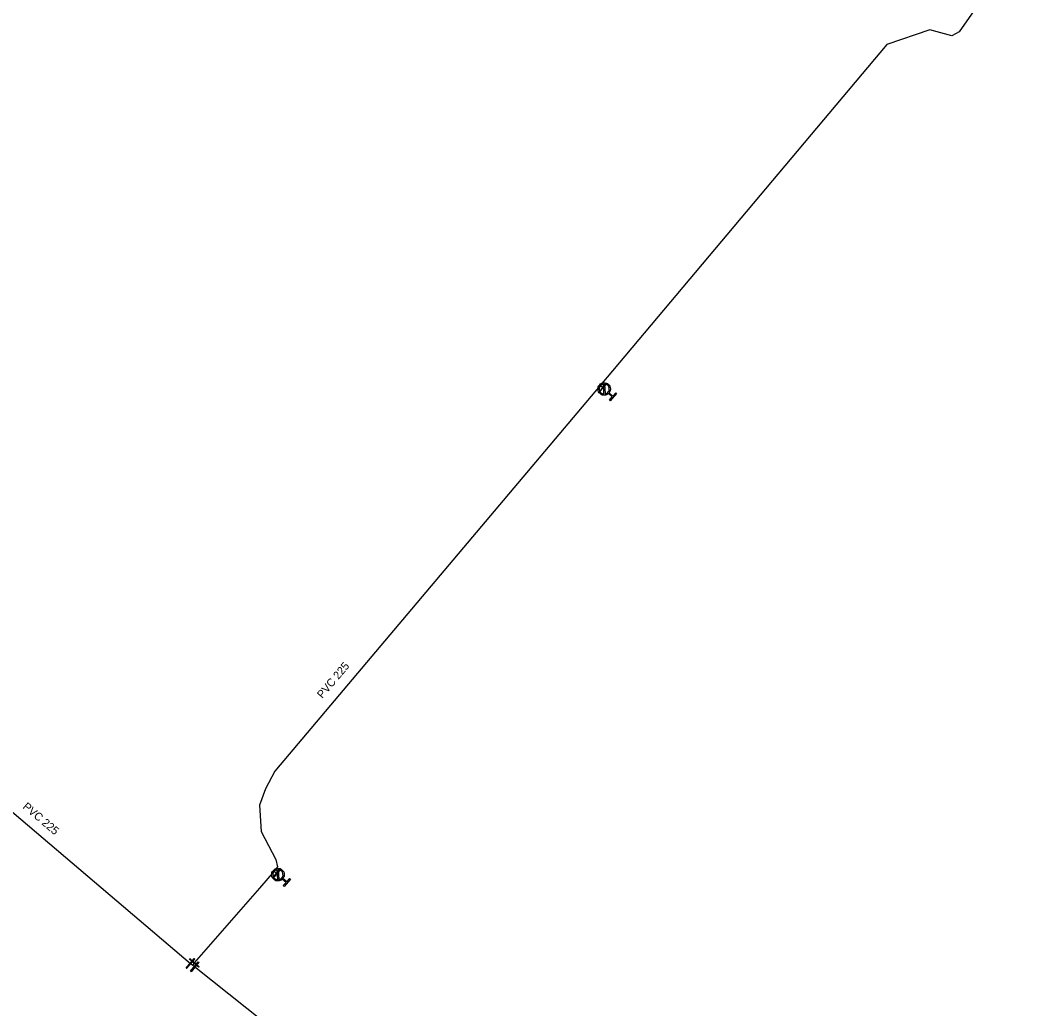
# Model space of a CAD drawing. Extents: x -643842 to -636370, y -1119190 to -1110210.
# Drawn here: x -640713.4 to -640550.3, y -1115738.1 to -1115577.6 of the extents above; entities that cross this region are included whole.
import ezdxf

# ---------------------------------------------------------------- set-up
doc = ezdxf.new("R2010")
doc.units = 0
for name, color, linetype in [('Default', 7, 'Continuous'), ('Level 16', 7, 'Continuous'), ('Level 20', 7, 'Continuous'), ('Level 21', 7, 'Continuous'), ('Level 23', 7, 'Continuous'), ('Level 33', 7, 'Continuous')]:
    doc.layers.add(name, color=color, linetype=linetype)

msp = doc.modelspace()

# ---------------------------------------------------------------- linework, layer by layer
at = {"layer": 'Default'}
for points in [[(-640617.92, -1115638.2), (-640618.18, -1115638.45), (-640618.55, -1115638.47), (-640618.96, -1115638.49), (-640619.27, -1115638.21), (-640619.58, -1115637.94), (-640619.6, -1115637.52), (-640619.62, -1115637.11), (-640619.34, -1115636.8), (-640619.07, -1115636.49), (-640618.66, -1115636.47), (-640618.24, -1115636.45), (-640617.93, -1115636.72), (-640617.62, -1115637), (-640617.6, -1115637.41), (-640617.58, -1115637.78), (-640617.8, -1115638.07)], [(-640618.73, -1115636.67), (-640619.01, -1115636.71), (-640619.2, -1115636.93), (-640619.43, -1115637.18), (-640619.41, -1115637.51), (-640619.39, -1115637.85), (-640619.14, -1115638.07), (-640618.92, -1115638.27), (-640618.65, -1115638.28)], [(-640618.46, -1115638.27), (-640618.19, -1115638.23), (-640617.99, -1115638.01), (-640617.77, -1115637.76), (-640617.78, -1115637.42), (-640617.8, -1115637.09), (-640618.05, -1115636.86), (-640618.27, -1115636.67), (-640618.55, -1115636.66)], [(-640670.88, -1115717.03), (-640671.14, -1115717.29), (-640671.5, -1115717.31), (-640671.92, -1115717.34), (-640672.23, -1115717.06), (-640672.54, -1115716.79), (-640672.57, -1115716.38), (-640672.6, -1115715.96), (-640672.32, -1115715.65), (-640672.05, -1115715.34), (-640671.64, -1115715.31), (-640671.23, -1115715.28), (-640670.91, -1115715.55), (-640670.6, -1115715.83), (-640670.57, -1115716.24), (-640670.54, -1115716.61), (-640670.76, -1115716.9)], [(-640671.72, -1115715.51), (-640671.99, -1115715.56), (-640672.18, -1115715.77), (-640672.4, -1115716.03), (-640672.38, -1115716.36), (-640672.36, -1115716.7), (-640672.1, -1115716.92), (-640671.88, -1115717.11), (-640671.61, -1115717.12)], [(-640671.42, -1115717.11), (-640671.15, -1115717.06), (-640670.95, -1115716.84), (-640670.73, -1115716.59), (-640670.76, -1115716.25), (-640670.78, -1115715.92), (-640671.03, -1115715.7), (-640671.25, -1115715.5), (-640671.53, -1115715.5)]]:
    msp.add_open_spline(points, degree=3, dxfattribs=at)
at = {"layer": 'Level 16'}
for points in [[(-640618.29, -1115636.74), (-640619.29, -1115637.86), (-640619.36, -1115637.79), (-640618.36, -1115636.68), (-640618.29, -1115636.74)], [(-640671.27, -1115715.58), (-640672.26, -1115716.71), (-640672.33, -1115716.64), (-640671.34, -1115715.51), (-640671.27, -1115715.58)], [(-640685.1, -1115730.02), (-640686.4, -1115731.54), (-640686.5, -1115731.46), (-640685.2, -1115729.94), (-640685.1, -1115730.02)], [(-640685.88, -1115729.94), (-640684.38, -1115731.25), (-640684.46, -1115731.34), (-640685.96, -1115730.03), (-640685.88, -1115729.94)], [(-640684.44, -1115730.52), (-640685.68, -1115732.08), (-640685.78, -1115732), (-640684.54, -1115730.44), (-640684.44, -1115730.52)]]:
    msp.add_lwpolyline(points, dxfattribs=at)
at = {"layer": 'Level 21'}
for points in [[(-640550.3, -1115564.07), (-640550.83, -1115564.84), (-640551.07, -1115565.27), (-640560.95, -1115579.51), (-640562.18, -1115580.12), (-640565.72, -1115579.18), (-640572.72, -1115581.54), (-640619.27, -1115636.87), (-640672.1, -1115699.48), (-640673.58, -1115702.36), (-640674.55, -1115705), (-640674.32, -1115709.29), (-640671.92, -1115713.83), (-640671.64, -1115715.04), (-640672.2, -1115715.76), (-640674.57, -1115718.49), (-640685.17, -1115730.64), (-640685.42, -1115730.98)], [(-640728.97, -1115694.03), (-640685.8, -1115730.74), (-640685.42, -1115730.98)], [(-640651.4, -1115758.11), (-640685.11, -1115731.26), (-640685.42, -1115730.98)]]:
    msp.add_lwpolyline(points, dxfattribs=at)
at = {"layer": 'Level 23'}
for points in [[(-640618.6, -1115637.47), (-640618.83, -1115637.27), (-640619.27, -1115636.87)], [(-640671.57, -1115716.31), (-640671.8, -1115716.11), (-640672.2, -1115715.76)]]:
    msp.add_lwpolyline(points, dxfattribs=at)
at = {"layer": 'Level 33'}
for points in [[(-640618.65, -1115638.28), (-640618.73, -1115636.67)], [(-640618.55, -1115636.66), (-640618.46, -1115638.27)], [(-640617.8, -1115638.07), (-640617.18, -1115638.61), (-640616.72, -1115638.1), (-640616.59, -1115638.22), (-640617.63, -1115639.39), (-640617.77, -1115639.26), (-640617.31, -1115638.75), (-640617.92, -1115638.2)], [(-640671.61, -1115717.12), (-640671.72, -1115715.51)], [(-640671.53, -1115715.5), (-640671.42, -1115717.11)], [(-640670.76, -1115716.9), (-640670.14, -1115717.43), (-640669.69, -1115716.92), (-640669.55, -1115717.04), (-640670.58, -1115718.21), (-640670.71, -1115718.09), (-640670.26, -1115717.57), (-640670.88, -1115717.03)]]:
    msp.add_lwpolyline(points, dxfattribs=at)

# ---------------------------------------------------------------- texts
at = {"layer": 'Level 20'}
for rotation, p in [(49.8425, (-640664.37, -1115687.8)), (319.6235, (-640713.12, -1115705.44))]:
    msp.add_text('PVC 225', height=1.3, rotation=rotation, dxfattribs=at).set_placement(p)

doc.saveas('drawing.dxf')
